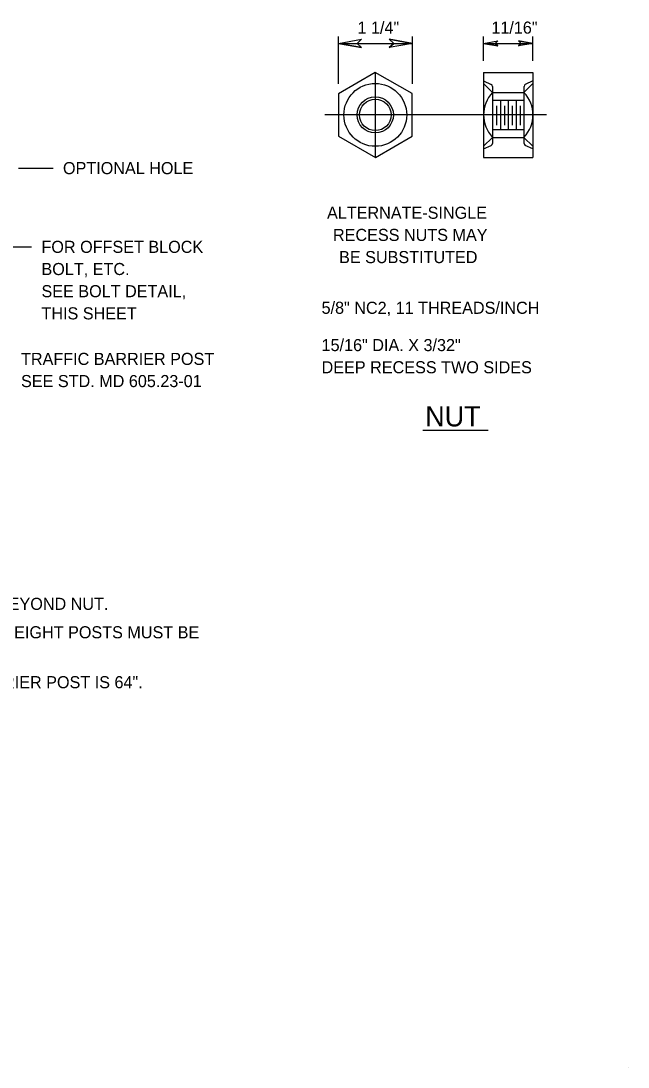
# Model space of a CAD drawing. Extents: x 12.4 to 19.6, y 6 to 16.1.
# Drawn here: x 16.61 to 19.62, y 5.99 to 11.18 of the extents above; entities that cross this region are included whole.
import ezdxf

# ---------------------------------------------------------------- set-up
doc = ezdxf.new("R2010")
doc.units = 0
for name, color, linetype in [('DETL-DIMS', 7, 'Continuous'), ('DETL-LINE', 7, 'Continuous'), ('DETL-NOTE', 7, 'Continuous'), ('DETL-PATT', 7, 'Continuous'), ('DETL-TITL', 7, 'Continuous'), ('TTLB-TEXT', 7, 'Continuous')]:
    doc.layers.add(name, color=color, linetype=linetype)

msp = doc.modelspace()

# ---------------------------------------------------------------- linework, layer by layer
at = {"layer": 'DETL-DIMS'}
for p, q in [((18.1845, 10.8637), (18.1845, 11.0981)), ((18.1845, 11.0648), (18.2989, 11.085)), ((18.1845, 11.0648), (18.5517, 11.0648)), ((18.1845, 11.0648), (18.2989, 11.0446)), ((18.2773, 11.0648), (18.2989, 11.085)), ((18.2989, 11.0446), (18.2773, 11.0648)), ((18.5517, 11.0648), (18.4373, 11.085)), ((18.4373, 11.085), (18.4589, 11.0648)), ((18.5517, 11.0648), (18.4373, 11.0446)), ((18.4589, 11.0648), (18.4373, 11.0446)), ((18.5517, 10.8637), (18.5517, 11.0981)), ((18.9047, 10.9781), (18.9047, 11.0981)), ((18.9047, 11.0645), (18.9762, 11.0771)), ((18.9047, 11.0645), (19.1495, 11.0645)), ((18.9047, 11.0645), (18.9762, 11.0519)), ((18.9627, 11.0645), (18.9762, 11.0771)), ((18.9762, 11.0519), (18.9627, 11.0645)), ((19.1495, 11.0645), (19.078, 11.0771)), ((19.078, 11.0771), (19.0915, 11.0645)), ((19.1495, 11.0645), (19.078, 11.0519)), ((19.0915, 11.0645), (19.078, 11.0519)), ((19.1495, 10.9781), (19.1495, 11.0981)), ((18.3676, 10.9205), (18.3676, 10.4983)), ((19.2169, 10.7097), (18.1173, 10.7097)), ((16.5974, 10.4457), (16.7702, 10.4457)), ((16.4887, 10.0551), (16.6615, 10.0551))]:
    msp.add_line(p, q, dxfattribs=at)
for points in [[(18.2989, 11.0446), (18.1845, 11.0648), (18.2989, 11.085), (18.2773, 11.0648)], [(18.4373, 11.085), (18.5517, 11.0648), (18.4373, 11.0446), (18.4589, 11.0648)], [(18.9762, 11.0519), (18.9047, 11.0645), (18.9762, 11.0771), (18.9627, 11.0645)], [(19.078, 11.0771), (19.1495, 11.0645), (19.078, 11.0519), (19.0915, 11.0645)]]:
    msp.add_lwpolyline(points, close=True, dxfattribs=at)
at = {"layer": 'DETL-LINE'}
for p, q in [((18.9047, 10.9205), (18.9047, 10.499)), ((18.9047, 10.9205), (19.1497, 10.9205)), ((19.1497, 10.9205), (19.1497, 10.499)), ((18.9495, 10.8211), (18.9049, 10.8656)), ((18.905, 10.8785), (18.9428, 10.8611)), ((18.9493, 10.851), (18.9493, 10.5685)), ((19.1052, 10.8211), (19.1497, 10.8656)), ((19.1054, 10.851), (19.1054, 10.5685)), ((19.1496, 10.8785), (19.1119, 10.8611)), ((18.9493, 10.8211), (19.1052, 10.8211)), ((18.9493, 10.7821), (19.1052, 10.7821)), ((18.9885, 10.7821), (18.9885, 10.6373)), ((19.0274, 10.7821), (19.0274, 10.6373)), ((19.0664, 10.7821), (19.0664, 10.6373)), ((18.9495, 10.5984), (18.9049, 10.5538)), ((18.9493, 10.6373), (19.1052, 10.6373)), ((18.9493, 10.5984), (19.1052, 10.5984)), ((19.1052, 10.5984), (19.1497, 10.5538)), ((18.905, 10.5409), (18.9428, 10.5583)), ((19.1496, 10.5409), (19.1119, 10.5583)), ((18.9047, 10.499), (19.1497, 10.499))]:
    msp.add_line(p, q, dxfattribs=at)
msp.add_lwpolyline([(18.5507, 10.6047), (18.5501, 10.8157), (18.3671, 10.9208), (18.1845, 10.8148), (18.1851, 10.6037), (18.3682, 10.4986)], close=True, dxfattribs=at)
for radius in [0.1559, 0.0897, 0.078]:
    msp.add_circle((18.3677, 10.7097), radius, dxfattribs=at)
for centre, radius, start, end in [((18.9382, 10.851), 0.0111, 0, 65.2132), ((19.1166, 10.851), 0.0111, 114.7868, 180), ((19.0662, 10.7097), 0.1615, 136.3972, 223.6028), ((18.9883, 10.7097), 0.1615, 316.3972, 43.6028), ((18.9382, 10.5685), 0.0111, 294.788, 0), ((19.1166, 10.5685), 0.0111, 180, 245.212)]:
    msp.add_arc(centre, radius, start, end, dxfattribs=at)
at = {"layer": 'DETL-PATT'}
for p, q in [((18.969, 10.7541), (18.969, 10.6587)), ((19.0079, 10.7541), (19.0079, 10.6587)), ((19.0469, 10.7541), (19.0469, 10.6587)), ((19.0859, 10.7541), (19.0859, 10.6587))]:
    msp.add_line(p, q, dxfattribs=at)
at = {"layer": 'DETL-TITL'}
msp.add_line((18.6043, 9.1453), (18.928, 9.1453), dxfattribs=at)
at = {"layer": 'TTLB-TEXT'}
msp.add_line((19.6217, 5.9855), (19.6217, 5.9855), dxfattribs=at)
msp.add_line((19.6217, 5.9855), (19.6217, 5.9855), dxfattribs=at)

# ---------------------------------------------------------------- texts
at = {"layer": 'DETL-NOTE'}
for s, p in [('1 1/4"', (18.2794, 11.1128)), ('11/16"', (18.9434, 11.1128)), ('OPTIONAL HOLE', (16.8182, 10.4157)), ('ALTERNATE-SINGLE', (18.1282, 10.1943)), ('RECESS NUTS MAY', (18.1577, 10.0843)), ('FOR OFFSET BLOCK', (16.7115, 10.0251)), ('BE SUBSTITUTED', (18.188, 9.9743)), ('BOLT, ETC.', (16.7115, 9.9151)), ('SEE BOLT DETAIL,', (16.7115, 9.8051)), ('5/8" NC2, 11 THREADS/INCH', (18.1012, 9.7227)), ('THIS SHEET', (16.7115, 9.6951)), ('15/16" DIA. X 3/32"', (18.1012, 9.5377)), ('TRAFFIC BARRIER POST', (16.6101, 9.4692)), ('DEEP RECESS TWO SIDES', (18.1012, 9.4277)), ('SEE STD. MD 605.23-01', (16.6101, 9.3592)), ('2. THE CONTRACTOR HAS THE OPTION TO USE SHORTER BOLTS WITH A MINIMUM OF 1/2" PROTRUSION BEYOND NUT.', (12.3748, 8.2539)), ("3. WITH ENGINEER'S APPROVAL, ONE POST CAN BE OMITTED WITHOUT OTHER CHANGES.  A MINIMUM OF EIGHT POSTS MUST BE", (12.3748, 8.1128)), ('4. EMBEDMENT DEPTH OF 6\'-0" TRAFFIC BARRIER POST IS 40". EMBEDMENT DEPTH OF 8\'-0" TRAFFIC BARRIER POST IS 64".', (12.3748, 7.8651))]:
    msp.add_text(s, height=0.06, dxfattribs=at).set_placement(p)
at = {"layer": 'DETL-TITL'}
msp.add_text('NUT', height=0.1, dxfattribs=at).set_placement((18.6154, 9.1642))

doc.saveas('drawing.dxf')
